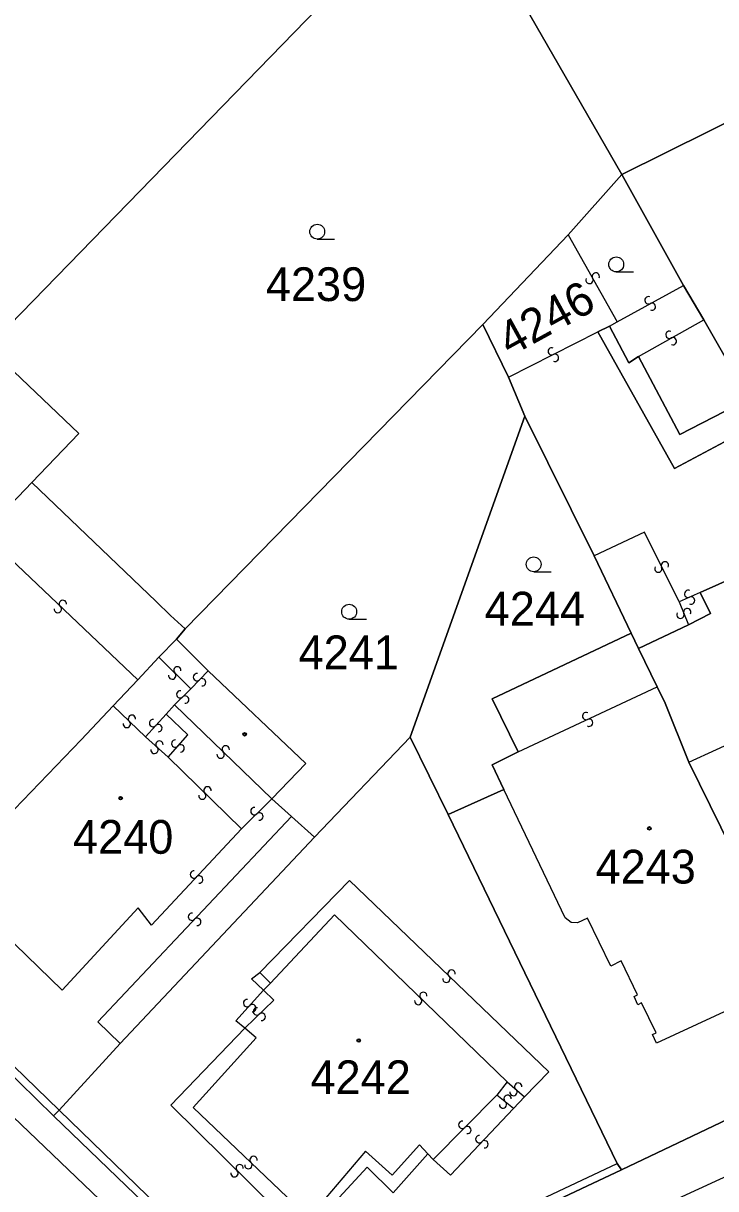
# Model space of a CAD drawing. Extents: x -598233 to -596890, y -1157848 to -1156431.
# Drawn here: x -598128.6 to -598093.7, y -1157113 to -1157054.3 of the extents above; entities that cross this region are included whole.
import ezdxf

# ---------------------------------------------------------------- set-up
doc = ezdxf.new("R2010")
doc.units = 0
for name, color, linetype in [('Level 1', 7, 'Continuous'), ('Level 13', 7, 'Continuous'), ('Level 3', 7, 'Continuous'), ('Level 4', 7, 'Continuous'), ('Level 5', 7, 'Continuous'), ('Level 60', 7, 'Continuous'), ('Vrstva 60', 7, 'Continuous')]:
    doc.layers.add(name, color=color, linetype=linetype)

msp = doc.modelspace()

# ---------------------------------------------------------------- linework, layer by layer
at = {"layer": 'Level 1'}
for points in [[(-598107.13, -1157046.77), (-598131.06, -1157071.39)], [(-598098.39, -1157061.95), (-598106.45, -1157047.94)], [(-598098.39, -1157061.95), (-598089.52, -1157057.55), (-598083.78, -1157054.53)], [(-598098.39, -1157061.95), (-598101.09, -1157064.98)], [(-598095.28, -1157067.53), (-598098.39, -1157061.95)], [(-598101.09, -1157064.98), (-598105.4, -1157069.5)], [(-598094.25, -1157069.26), (-598095.28, -1157067.53)], [(-598105.4, -1157069.5), (-598120.39, -1157084.83)], [(-598105.4, -1157069.5), (-598104.1, -1157072.16)], [(-598099.59, -1157069.87), (-598099.01, -1157069.59)], [(-598099.01, -1157069.59), (-598098.04, -1157071.43), (-598097.55, -1157071.11)], [(-598092.03, -1157073.14), (-598094.25, -1157069.26)], [(-598094.44, -1157083), (-598090.68, -1157081.33), (-598090.32, -1157080.82), (-598090.53, -1157080.02), (-598093.22, -1157075.41), (-598095.73, -1157076.75), (-598099.59, -1157069.87)], [(-598131.8, -1157073.95), (-598129.39, -1157071.53), (-598125.76, -1157074.99), (-598128.13, -1157077.46)], [(-598097.55, -1157071.11), (-598095.46, -1157075.05), (-598093.22, -1157073.88)], [(-598104.1, -1157072.16), (-598103.27, -1157074.12)], [(-598103.27, -1157074.12), (-598109.06, -1157090.3)], [(-598103.27, -1157074.12), (-598099.78, -1157081.15)], [(-598128.13, -1157077.46), (-598121.86, -1157083.46), (-598121.14, -1157084.17), (-598120.39, -1157084.83)], [(-598099.78, -1157081.15), (-598097.92, -1157085.06)], [(-598095.03, -1157084.64), (-598093.91, -1157084.07), (-598094.44, -1157083)], [(-598120.39, -1157084.83), (-598120.83, -1157085.36)], [(-598103.62, -1157091.04), (-598104.92, -1157088.37), (-598097.92, -1157085.06)], [(-598097.92, -1157085.06), (-598097.55, -1157085.83)], [(-598097.55, -1157085.83), (-598095.03, -1157084.64)], [(-598120.83, -1157085.36), (-598121.73, -1157086.26)], [(-598120.83, -1157085.36), (-598119.23, -1157086.95)], [(-598097.55, -1157085.83), (-598096.6, -1157087.76)], [(-598121.73, -1157086.26), (-598122.79, -1157087.4)], [(-598122.79, -1157087.4), (-598124.02, -1157088.71)], [(-598119.23, -1157086.95), (-598114.31, -1157091.62), (-598116.02, -1157093.41)], [(-598095.01, -1157091.55), (-598096.2, -1157088.58), (-598096.6, -1157087.76)], [(-598124.02, -1157088.71), (-598125.63, -1157090.43), (-598132.37, -1157097.41)], [(-598109.06, -1157090.3), (-598113.88, -1157095.34)], [(-598109.06, -1157090.3), (-598107.14, -1157094.19)], [(-598104.34, -1157092.93), (-598104.93, -1157091.69), (-598103.62, -1157091.04)], [(-598095.01, -1157091.55), (-598089.63, -1157102.48)], [(-598107.14, -1157094.19), (-598104.34, -1157092.93)], [(-598116.02, -1157093.41), (-598115.04, -1157094.3)], [(-598115.04, -1157094.3), (-598113.88, -1157095.34)], [(-598107.14, -1157094.19), (-598098.63, -1157111.78)], [(-598113.88, -1157095.34), (-598123.68, -1157105.73)], [(-598127.04, -1157109.38), (-598132.19, -1157104.33), (-598135.7, -1157101.01)], [(-598123.68, -1157105.73), (-598126.75, -1157109.09)], [(-598087.37, -1157106.84), (-598098.41, -1157112.1)], [(-598126.75, -1157109.09), (-598127.04, -1157109.38)], [(-598117.44, -1157118.61), (-598127.04, -1157109.38)], [(-598098.63, -1157111.78), (-598098.41, -1157112.1)], [(-598098.41, -1157112.1), (-598113.81, -1157119.36), (-598114.74, -1157119.5), (-598115.57, -1157119.43), (-598116.54, -1157119.13), (-598117.44, -1157118.61)]]:
    msp.add_lwpolyline(points, dxfattribs=at)
at = {"layer": 'Level 13'}
for centre, start, end in [((-598100.021, -1157067.259), 156.47875, 29.06875), ((-598099.698, -1157067.081), 336.69321, 208.79121), ((-598097.047, -1157068.277), 66.01913, 298.11713), ((-598096.872, -1157068.602), 245.80468, 118.39468), ((-598095.989, -1157070.018), 66.64799, 298.74598), ((-598095.811, -1157070.341), 246.43353, 119.02353), ((-598101.922, -1157070.855), 64.29239, 296.39039), ((-598101.757, -1157071.184), 244.07794, 116.66794), ((-598096.215, -1157081.639), 333.59296, 206.18296), ((-598096.546, -1157081.801), 153.80742, 25.90542), ((-598095.045, -1157083.072), 61.52073, 294.11073), ((-598094.895, -1157083.409), 241.73519, 113.83318), ((-598126.818, -1157083.843), 173.92089, 46.01889), ((-598126.563, -1157083.577), 353.70644, 226.29644), ((-598095.088, -1157083.992), 329.42917, 201.52716), ((-598095.431, -1157084.128), 149.21471, 21.80471), ((-598120.79, -1157086.93), 352.51415, 225.10415), ((-598121.051, -1157087.19), 172.7286, 44.8266), ((-598119.801, -1157087.271), 83.33291, 315.43091), ((-598119.538, -1157087.529), 263.11845, 135.70845), ((-598120.648, -1157088.138), 82.02123, 314.11923), ((-598120.391, -1157088.402), 261.80678, 134.39678), ((-598100.187, -1157089.232), 62.41643, 294.51443), ((-598123.338, -1157089.632), 173.23245, 45.82245), ((-598123.081, -1157089.368), 353.4469, 225.5449), ((-598122.016, -1157089.586), 85.06019, 317.65019), ((-598121.744, -1157089.835), 265.27464, 137.37264), ((-598100.033, -1157089.567), 242.20198, 114.79198), ((-598121.945, -1157090.935), 174.80897, 47.39897), ((-598121.694, -1157090.665), 355.02342, 227.12142), ((-598120.898, -1157090.618), 86.401, 318.49899), ((-598120.622, -1157090.861), 266.18654, 138.77654), ((-598118.352, -1157090.908), 353.16753, 225.75753), ((-598118.609, -1157091.172), 173.38199, 45.47998), ((-598119.529, -1157093.242), 173.02039, 45.61039), ((-598119.27, -1157092.979), 353.23485, 225.33284), ((-598116.908, -1157094.027), 81.80547, 313.90346), ((-598116.652, -1157094.292), 261.59101, 134.18101), ((-598119.954, -1157097.214), 84.04914, 316.63914), ((-598119.687, -1157097.467), 264.2636, 136.3616), ((-598120.053, -1157099.343), 83.84045, 316.43045), ((-598119.787, -1157099.598), 264.0549, 136.1529), ((-598106.971, -1157102.208), 353.56562, 225.66361), ((-598107.228, -1157102.472), 173.35116, 45.94116), ((-598108.391, -1157103.328), 353.12817, 225.71817), ((-598117.275, -1157103.694), 84.896, 316.994), ((-598117.005, -1157103.945), 264.68154, 137.27154), ((-598108.649, -1157103.591), 173.34262, 45.44062), ((-598116.786, -1157104.116), 81.17924, 313.27724), ((-598116.533, -1157104.383), 260.96479, 133.55479), ((-598103.608, -1157107.901), 356.60913, 228.70713), ((-598104.145, -1157108.516), 358.91185, 231.50185), ((-598103.851, -1157108.179), 176.39467, 48.98467), ((-598104.376, -1157108.804), 179.12631, 51.22431), ((-598106.43, -1157109.83), 82.51305, 315.10305), ((-598106.17, -1157110.091), 262.7275, 134.8255), ((-598105.573, -1157110.553), 83.64501, 316.23501), ((-598105.307, -1157110.808), 263.85947, 135.95746), ((-598116.952, -1157111.597), 353.51384, 226.10384), ((-598117.65, -1157112.01), 352.50343, 225.09343), ((-598117.209, -1157111.862), 173.7283, 45.82629), ((-598117.911, -1157112.27), 172.71788, 44.81588)]:
    msp.add_arc(centre, 0.184, start, end, dxfattribs=at)
at = {"layer": 'Level 3'}
msp.add_line((-598117.44, -1157120.53), (-598232.89, -1157010.336), dxfattribs=at)
for points in [[(-598101.09, -1157064.98), (-598098.63, -1157069.36)], [(-598098.63, -1157069.36), (-598095.28, -1157067.53)], [(-598099.01, -1157069.59), (-598098.63, -1157069.36)], [(-598097.55, -1157071.11), (-598094.25, -1157069.26)], [(-598104.1, -1157072.16), (-598099.59, -1157069.87)], [(-598122.79, -1157087.4), (-598130.58, -1157080.02), (-598128.13, -1157077.46)], [(-598095.5, -1157083.48), (-598097.25, -1157079.96), (-598099.78, -1157081.15)], [(-598024.88, -1157080.48), (-598039.36, -1157087.11), (-598064.01, -1157098.67), (-598088.17, -1157110.14), (-598113.57, -1157121.84), (-598114.94, -1157121.93), (-598116.45, -1157121.47), (-598117.44, -1157120.53)], [(-598094.44, -1157083), (-598095.5, -1157083.48)], [(-598095.5, -1157083.48), (-598095.03, -1157084.64)], [(-598120.11, -1157087.86), (-598121.73, -1157086.26)], [(-598120.11, -1157087.86), (-598119.23, -1157086.95)], [(-598120.93, -1157088.67), (-598120.11, -1157087.86)], [(-598103.62, -1157091.04), (-598096.6, -1157087.76)], [(-598095.01, -1157091.55), (-598086.64, -1157087.73), (-598084.82, -1157091.63), (-598085.65, -1157092.06), (-598084.6, -1157094.29)], [(-598124.02, -1157088.71), (-598122.39, -1157090.28)], [(-598121.36, -1157089.14), (-598122.39, -1157090.28)], [(-598120.93, -1157088.67), (-598121.36, -1157089.14)], [(-598121.26, -1157091.31), (-598120.27, -1157090.17), (-598121.36, -1157089.14)], [(-598116.02, -1157093.41), (-598120.93, -1157088.67)], [(-598122.39, -1157090.28), (-598121.26, -1157091.31)], [(-598121.26, -1157091.31), (-598117.55, -1157094.91)], [(-598089.63, -1157102.48), (-598096.64, -1157105.71), (-598096.84, -1157105.28), (-598096.66, -1157105.19), (-598097.39, -1157103.68), (-598097.58, -1157103.78), (-598097.77, -1157103.37), (-598097.59, -1157103.28), (-598098.42, -1157101.56), (-598098.94, -1157101.84), (-598100.11, -1157099.42), (-598100.62, -1157099.65), (-598100.94, -1157099.64), (-598101.24, -1157099.39), (-598104.34, -1157092.93)], [(-598117.55, -1157094.91), (-598116.02, -1157093.41)], [(-598115.04, -1157094.3), (-598124.79, -1157104.64), (-598123.68, -1157105.73)], [(-598117.55, -1157094.91), (-598122.09, -1157099.76), (-598122.77, -1157098.9), (-598126.59, -1157103.05), (-598128.98, -1157100.72)], [(-598116.64, -1157102.15), (-598112.12, -1157097.52), (-598102.07, -1157107.16), (-598103.29, -1157108.42)], [(-598104.16, -1157107.67), (-598112.87, -1157099.25), (-598116.1, -1157102.69)], [(-598116.44, -1157103.05), (-598117.06, -1157102.48), (-598116.64, -1157102.15)], [(-598116.1, -1157102.69), (-598116.64, -1157102.15)], [(-598117.39, -1157104.95), (-598117.85, -1157104.59), (-598116.44, -1157103.05)], [(-598117.39, -1157104.95), (-598115.92, -1157103.54), (-598116.44, -1157103.05)], [(-598116.44, -1157103.05), (-598116.1, -1157102.69)], [(-598126.75, -1157109.09), (-598131.93, -1157104.09)], [(-598108.17, -1157111.29), (-598109.92, -1157113.25), (-598111.23, -1157111.97), (-598114.44, -1157115.44), (-598121.12, -1157108.84), (-598117.39, -1157104.95)], [(-598108.17, -1157111.29), (-598108.59, -1157110.84), (-598109.97, -1157112.37), (-598111.31, -1157111.16), (-598114.16, -1157114.52), (-598120, -1157108.95), (-598116.82, -1157105.44), (-598117.39, -1157104.95)], [(-598104.16, -1157107.67), (-598104.69, -1157108.33)], [(-598104.16, -1157107.67), (-598103.29, -1157108.42)], [(-598104.69, -1157108.33), (-598107.9, -1157111.58)], [(-598103.84, -1157109), (-598104.69, -1157108.33)], [(-598103.29, -1157108.42), (-598103.84, -1157109)], [(-598126.75, -1157109.09), (-598117.3, -1157118.25), (-598115.54, -1157119.08), (-598113.97, -1157119.01), (-598098.63, -1157111.78)], [(-598103.84, -1157109), (-598107.03, -1157112.36), (-598107.9, -1157111.58)], [(-598107.9, -1157111.58), (-598108.17, -1157111.29)]]:
    msp.add_lwpolyline(points, dxfattribs=at)
at = {"layer": 'Level 5'}
for p, q in [((-598113.74, -1157065.2), (-598112.865, -1157065.2)), ((-598098.67, -1157066.85), (-598097.795, -1157066.85)), ((-598102.83, -1157081.96), (-598101.955, -1157081.96)), ((-598112.13, -1157084.35), (-598111.255, -1157084.35))]:
    msp.add_line(p, q, dxfattribs=at)
for centre, radius in [((-598113.74, -1157064.825), 0.375), ((-598098.67, -1157066.475), 0.375), ((-598102.83, -1157081.585), 0.375), ((-598112.13, -1157083.975), 0.375), ((-598117.4, -1157090.15), 0.09), ((-598117.4, -1157090.15), 0.0521), ((-598123.65, -1157093.37), 0.09), ((-598123.65, -1157093.37), 0.0521), ((-598097, -1157094.89), 0.09), ((-598097, -1157094.89), 0.0521), ((-598111.65, -1157105.58), 0.09), ((-598111.65, -1157105.58), 0.0521)]:
    msp.add_circle(centre, radius, dxfattribs=at)
at = {"layer": 'Level 60'}
for points in [[(-598143.19, -1157059.48), (-598129.11, -1157044.84), (-598115.98, -1157031.27), (-598109.57, -1157042.5), (-598107.13, -1157046.77), (-598131.06, -1157071.39), (-598131.54, -1157070.98), (-598139.69, -1157062.97)], [(-598089.52, -1157057.55), (-598098.39, -1157061.95), (-598106.45, -1157047.94), (-598100.54, -1157044.58), (-598082.1, -1157034.12), (-598074.56, -1157049.97), (-598075.58, -1157050.49), (-598077.39, -1157051.4), (-598080.58, -1157052.94), (-598081.48, -1157053.39), (-598083.78, -1157054.53)], [(-598131.93, -1157072.42), (-598131.06, -1157071.39), (-598107.13, -1157046.77), (-598106.45, -1157047.94), (-598098.39, -1157061.95), (-598101.09, -1157064.98), (-598105.4, -1157069.5), (-598120.39, -1157084.83), (-598121.14, -1157084.17), (-598121.86, -1157083.46), (-598128.13, -1157077.46), (-598125.76, -1157074.99), (-598129.39, -1157071.53), (-598131.8, -1157073.95), (-598132.05, -1157073.71), (-598131.37, -1157072.98)], [(-598075.98, -1157087.66), (-598082.34, -1157090.54), (-598092.03, -1157073.14), (-598094.25, -1157069.26), (-598095.28, -1157067.53), (-598098.39, -1157061.95), (-598089.52, -1157057.55), (-598083.78, -1157054.53), (-598074.89, -1157073.45), (-598071.75, -1157080.04), (-598078.12, -1157083.07)], [(-598120.83, -1157085.36), (-598120.39, -1157084.83), (-598105.4, -1157069.5), (-598104.1, -1157072.16), (-598103.27, -1157074.12), (-598109.06, -1157090.3), (-598113.88, -1157095.34), (-598115.04, -1157094.3), (-598116.02, -1157093.41), (-598114.31, -1157091.62), (-598119.23, -1157086.95)], [(-598134.44, -1157075.06), (-598131.93, -1157072.42), (-598131.37, -1157072.98), (-598132.05, -1157073.71), (-598131.8, -1157073.95), (-598129.39, -1157071.53), (-598125.76, -1157074.99), (-598128.13, -1157077.46), (-598121.86, -1157083.46), (-598121.14, -1157084.17), (-598120.39, -1157084.83), (-598120.83, -1157085.36), (-598121.73, -1157086.26), (-598122.79, -1157087.4), (-598124.02, -1157088.71), (-598125.63, -1157090.43), (-598132.37, -1157097.41), (-598135.45, -1157100.82), (-598135.7, -1157101.01), (-598143.6, -1157093.49), (-598145.41, -1157091.7), (-598148.09, -1157089.2), (-598147.81, -1157088.96)], [(-598109.06, -1157090.3), (-598103.27, -1157074.12), (-598099.78, -1157081.15), (-598097.92, -1157085.06), (-598104.92, -1157088.37), (-598103.62, -1157091.04), (-598104.93, -1157091.69), (-598104.34, -1157092.93), (-598107.14, -1157094.19)], [(-598098.63, -1157111.78), (-598107.14, -1157094.19), (-598104.34, -1157092.93), (-598104.93, -1157091.69), (-598103.62, -1157091.04), (-598104.92, -1157088.37), (-598097.92, -1157085.06), (-598097.55, -1157085.83), (-598096.6, -1157087.76), (-598096.2, -1157088.58), (-598095.01, -1157091.55), (-598089.63, -1157102.48), (-598087.49, -1157106.62), (-598087.37, -1157106.84), (-598098.41, -1157112.1)], [(-598121.73, -1157086.26), (-598120.83, -1157085.36), (-598119.23, -1157086.95), (-598114.31, -1157091.62), (-598116.02, -1157093.41), (-598115.04, -1157094.3), (-598113.88, -1157095.34), (-598123.68, -1157105.73), (-598126.75, -1157109.09), (-598127.04, -1157109.38), (-598132.19, -1157104.33), (-598135.7, -1157101.01), (-598135.45, -1157100.82), (-598132.37, -1157097.41), (-598125.63, -1157090.43), (-598124.02, -1157088.71), (-598122.79, -1157087.4)], [(-598123.68, -1157105.73), (-598113.88, -1157095.34), (-598109.06, -1157090.3), (-598107.14, -1157094.19), (-598098.63, -1157111.78), (-598098.41, -1157112.1), (-598113.81, -1157119.36), (-598114.74, -1157119.5), (-598115.57, -1157119.43), (-598116.54, -1157119.13), (-598117.44, -1157118.61), (-598127.04, -1157109.38), (-598126.75, -1157109.09)]]:
    msp.add_lwpolyline(points, close=True, dxfattribs=at)
for points in [[(-598090.68, -1157081.33), (-598094.44, -1157083), (-598093.91, -1157084.07), (-598095.03, -1157084.64), (-598097.55, -1157085.83), (-598097.92, -1157085.06), (-598099.78, -1157081.15), (-598103.27, -1157074.12), (-598104.1, -1157072.16), (-598105.4, -1157069.5), (-598101.09, -1157064.98), (-598098.39, -1157061.95), (-598095.28, -1157067.53), (-598094.25, -1157069.26), (-598092.03, -1157073.14)], [(-598093.22, -1157075.41), (-598095.73, -1157076.75), (-598099.59, -1157069.87), (-598099.01, -1157069.59), (-598098.04, -1157071.43), (-598097.55, -1157071.11), (-598095.46, -1157075.05), (-598093.22, -1157073.88)], [(-598093.22, -1157073.88), (-598095.46, -1157075.05), (-598097.55, -1157071.11), (-598098.04, -1157071.43), (-598099.01, -1157069.59), (-598099.59, -1157069.87), (-598095.73, -1157076.75), (-598093.22, -1157075.41)], [(-598089.63, -1157102.48), (-598095.01, -1157091.55), (-598096.2, -1157088.58), (-598096.6, -1157087.76), (-598097.55, -1157085.83), (-598095.03, -1157084.64), (-598093.91, -1157084.07), (-598094.44, -1157083), (-598090.68, -1157081.33)], [(-598023.35, -1157090.35), (-598117.4, -1157134.54), (-598117.42, -1157133.54), (-598117.44, -1157130.35), (-598117.44, -1157126.68), (-598117.44, -1157120.53), (-598117.44, -1157118.61), (-598116.54, -1157119.13), (-598115.57, -1157119.43), (-598114.74, -1157119.5), (-598113.81, -1157119.36), (-598098.41, -1157112.1), (-598087.37, -1157106.84), (-598076.01, -1157101.52), (-598070.65, -1157099.03), (-598064.28, -1157096), (-598061.57, -1157094.79), (-598057.78, -1157092.99), (-598051.49, -1157090.01)]]:
    msp.add_lwpolyline(points, dxfattribs=at)
at = {"layer": 'Vrstva 60'}
msp.add_lwpolyline([(-598230.25, -1157027.16), (-598159.23, -1157094.89), (-598157.01, -1157097.09), (-598155.74, -1157098.35), (-598136.59, -1157116.46), (-598129.31, -1157123.39), (-598117.4, -1157134.54), (-598117.42, -1157133.54), (-598117.44, -1157130.35), (-598117.44, -1157118.61), (-598127.04, -1157109.38), (-598132.19, -1157104.33), (-598135.7, -1157101.01), (-598143.6, -1157093.49), (-598145.41, -1157091.7), (-598148.09, -1157089.2), (-598151.37, -1157086.03), (-598160.37, -1157077.44), (-598171.46, -1157066.92), (-598172.39, -1157066), (-598184.32, -1157054.57), (-598196.28, -1157043.23)], dxfattribs=at)

# ---------------------------------------------------------------- texts
at = {"layer": 'Level 4'}
for s, p in [('4239', (-598116.33, -1157068.32)), ('4244', (-598105.297, -1157084.67)), ('4241', (-598114.68, -1157086.87)), ('4240', (-598126.05, -1157096.17)), ('4243', (-598099.714, -1157097.67)), ('4242', (-598114.08, -1157108.28))]:
    msp.add_text(s, height=1.7, dxfattribs=at).set_placement(p)
msp.add_text('4246', height=1.7, rotation=28.8, dxfattribs=at).set_placement((-598104.02, -1157071.14))

doc.saveas('drawing.dxf')
